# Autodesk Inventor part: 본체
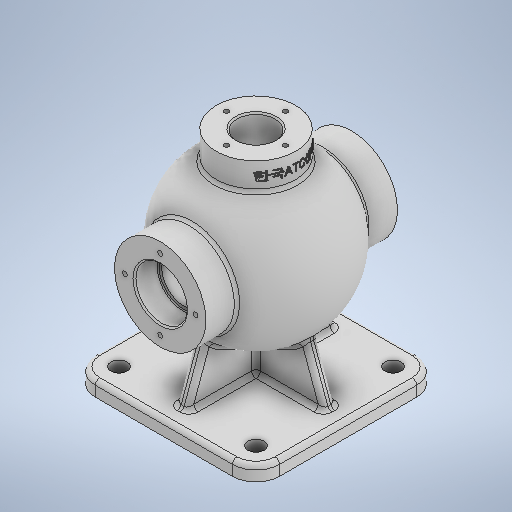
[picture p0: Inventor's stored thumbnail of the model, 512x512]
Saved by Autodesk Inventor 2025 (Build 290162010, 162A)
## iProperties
Created: 2024-07
Part Number: 본체
Material: 일반
Document SubType Name: Modeling
Designer: Admin
Density: 1 g/cm^3
Appearance: 기본값
Author: Admin
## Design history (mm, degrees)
sketch "스케치1"
  geometry: L1 (46.5, 62.5)-(-46.5, 62.5); L2 (-62.5, 46.5)-(-62.5, -46.5); L3 (-46.5, -62.5)-(46.5, -62.5); L4 (62.5, -46.5)-(62.5, 46.5); L5 (62.5, 62.5)-(-62.5, -62.5); L6 (-62.5, 62.5)-(62.5, -62.5); A1 r 16 centre (46.5, -46.5) between (46.5, -62.5) and (62.5, -46.5); A2 r 16 centre (-46.5, -46.5) between (-62.5, -46.5) and (-46.5, -62.5); A3 r 16 centre (-46.5, 46.5) between (-46.5, 62.5) and (-62.5, 46.5); A4 r 16 centre (46.5, 46.5) between (62.5, 46.5) and (46.5, 62.5); 1 further point
  constraints: 12 end point, 8 point on circle, 8 point on line, 8 tangent, 4 centre point, 3 equal radius, 2 midpoint, 2 parallel, 1 horizontal, 1 perpendicular
  dimensions: "d0" = 125 distance of L5.end L6.end; "d1" = 125 distance of L6.end L5.start (= d0); "d2" = 16 radius of A1
extrude "돌출1" new body sketch "스케치1" distance "d3" = 10; taper "d4" = 0 deg
sketch "스케치2"
  geometry: L1 (-50.5, -4)-(50.5, -4); L2 (50.5, -4)-(50.5, 4); L3 (50.5, 4)-(-50.5, 4); L4 (-50.5, 4)-(-50.5, -4); L5 (-50.5, -4)-(50.5, 4); L6 (50.5, -4)-(-50.5, 4); L7 (-4, 50.5)-(4, 50.5); L8 (4, 50.5)-(4, -50.5); L9 (4, -50.5)-(-4, -50.5); L10 (-4, -50.5)-(-4, 50.5); L11 (-4, 50.5)-(4, -50.5); L12 (4, 50.5)-(-4, -50.5); L13 (-62.5, 46.5)-(-62.5, -46.5) reference; L14 (46.5, 62.5)-(-46.5, 62.5) reference; L15 (62.5, -46.5)-(62.5, 46.5) reference; L16 (-46.5, -62.5)-(46.5, -62.5) reference; 5 further points
  constraints: 24 end point, 4 midpoint, 4 parallel, 2 horizontal, 2 perpendicular
  dimensions: "d5" = 8 distance of L3.end L1.start; "d6" = 8 distance of L7.start L7.end; "d7" = 12 distance between parallel lines of L13 L4; "d8" = 12 distance between parallel lines of L14 L7; "d114" = 12 distance between parallel lines of L15 L2 (derived); "d115" = 12 distance between parallel lines of L16 L9 (derived)
extrude "돌출2" join sketch "스케치2" distance "d9" = 85; taper "d10" = 0 deg
sketch "스케치3"
  geometry: L1 (0, 0)-(46.5, 0) reference; L2 (0, 0)-(0, 85) reference; L3 (46.5, 85)-(0, 85) reference; L4 (46.5, 0)-(46.5, 85) reference; L5 (54.5, 0)-(101, 0) reference; L6 (54.5, 0)-(54.5, 85) reference; L7 (101, 85)-(54.5, 85) reference; L8 (101, 0)-(101, 85) reference; L9 (0, 0)-(30.937, 85); L10 (101, 0)-(70.063, 85); L11 (-12, -10)-(-12, 0) reference; L12 (113, -10)-(113, 0) reference; 1 further point
  constraints: 4 end point, 2 point on line
  dimensions: "d11" = 20 deg angle of L11 L9; "d12" = 20 deg angle of L12 L10
extrude "돌출3" cut sketch "스케치3" stored distance "d13" = 85; taper "d14" = 0 deg
sketch "스케치4"
  geometry: L1 (-54.5, 0)-(-8, 0) reference; L2 (-54.5, 0)-(-54.5, 85) reference; L3 (-8, 85)-(-54.5, 85) reference; L4 (-8, 0)-(-8, 85) reference; L5 (0, 0)-(46.5, 0) reference; L6 (0, 0)-(0, 85) reference; L7 (46.5, 85)-(0, 85) reference; L8 (46.5, 0)-(46.5, 85) reference; L9 (-54.5, 0)-(-23.563, 85); L10 (15.563, 85)-(46.5, 0); L11 (-66.5, -10)-(-66.5, 0) reference; L12 (58.5, -10)-(58.5, 0) reference; 1 further point
  constraints: 4 end point, 2 point on line
  dimensions: "d15" = 20 deg angle of L11 L9; "d16" = 20 deg angle of L12 L10
extrude "돌출4" cut sketch "스케치4" distance "d17" = 10; taper "d18" = 0 deg
sketch "스케치5"
  geometry: L1 (-4, 10)-(-4, 95); L2 (4, 10)-(-4, 10); L3 (4, 95)-(4, 10); L4 (-4, 95)-(4, 95); L5 (0, 0)-(0, 85); C1 r 31 at (0, 85)
  constraints: 4 end point, 1 centre point, 1 coincident, 1 parallel
  dimensions: "d23" = 85 distance of L5.start L5.end; "d24" = 62 diameter of C1
extrude "돌출6" join sketch "스케치5" stored distance "d25" = 130; taper "d26" = 0 deg
sketch "스케치7"
  geometry: L1 (0, 0)-(31, 0); L2 (31, 0)-(85, 0); L3 (85, 0)-(127.511, 0); L4 (139, 0)-(31, 0); A1 r 54 centre (85, 0) between (31, 0) and (139, 0); A2 r 54 centre (85, 0) between (139, 0) and (31, 0); 1 further point
  constraints: 8 end point, 4 point on circle, 3 horizontal, 2 centre point, 1 coincident, 1 collinear, 1 point on line
  dimensions: "d27" = 85 distance of L1.start L2.end; "d28" = 108 diameter of A1
revolve "회전1" sketch "스케치7" stored, may be unused: angle "d29" = 90 deg
node "작업 평면1"
sketch "스케치8"
  geometry: C1 r 27 at (0, 0); 1 further point
  constraints: 1 centre point, 1 coincident
  dimensions: "d31" = 54 diameter of C1
extrude "돌출7" join sketch "스케치8" distance "d32" = 65; taper "d33" = 0 deg
fillet "모깎기1" dims "d34" = 3
fillet "모깎기2" dims "d35" = 3
fillet "모깎기3" dims "d36" = 3
sketch "스케치9"
  geometry: C1 r 31 at (0, 0) reference; 2 further points
  constraints: 1 coincident
hole "구멍1" sketch "스케치9" at (0, 0) diameter "d37" = 35; stored, may be unused: countersink angle "d41" = 90 deg, drill point angle "d43" = 0 deg; dims "d38" = 6, "d39" = 4, "d40" = 2, "d42" = 16
sketch "스케치10"
  geometry: C1 r 31 at (0, 0) reference; 2 further points
  constraints: 1 coincident
hole "구멍2" sketch "스케치10" at (0, 0) diameter "d44" = 35; stored, may be unused: countersink angle "d48" = 90 deg, drill point angle "d50" = 0 deg; dims "d45" = 6, "d46" = 4, "d47" = 2, "d49" = 16
sketch "스케치11"
  geometry: C1 r 17.5 at (0, 0) reference; 2 further points
  constraints: 1 coincident
hole "구멍3" sketch "스케치11" at (0, 0) diameter "d51" = 30; stored, may be unused: countersink angle "d55" = 90 deg, drill point angle "d57" = 0 deg; dims "d52" = 6, "d53" = 4, "d54" = 2, "d56" = 16
fillet "모깎기4" dims "d58" = 0.6
sketch "스케치12"
  geometry: C1 r 27 at (0, 0) reference; 2 further points
  constraints: 1 coincident
hole "구멍4" sketch "스케치12" at (0, 0) diameter "d59" = 26; stored, may be unused: countersink angle "d63" = 90 deg, drill point angle "d65" = 0 deg; dims "d60" = 6, "d61" = 4, "d62" = 2, "d64" = 45
chamfer "모따기1" distance "d66" = 1; stored, may be unused: second distance "d67" = 2, angle "d68" = 45 deg
chamfer "모따기2" distance "d69" = 1; stored, may be unused: second distance "d70" = 2, angle "d71" = 45 deg
chamfer "모따기3" distance "d72" = 1; stored, may be unused: second distance "d73" = 2, angle "d74" = 45 deg
sketch "스케치13"
  geometry: L1 (0, 0)-(0, 129); L2 (0, 129)-(0, 41); L3 (0, 129)-(0, 156.877); C1 r 15 at (0, 85) reference; A1 r 44 centre (0, 85) between (0, 129) and (0, 41); A2 r 44 centre (0, 85) between (0, 41) and (0, 129)
  constraints: 6 end point, 4 point on circle, 2 centre point, 2 vertical, 1 coincident, 1 point on line
  dimensions: "d75" = 88 diameter of A1
revolve "회전2" sketch "스케치13" stored, may be unused: angle "d76" = 90 deg
sketch "스케치14" dims "d81" = 48
  geometry: L1 (0, 0)-(0, 24); C1 r 18.5 at (0, 0) reference; 2 further points
  constraints: 2 coincident, 2 end point, 1 vertical, 1 vertical alignment, 2 other
hole "구멍5" sketch "스케치14" at (0, 24) diameter "d82" = 3.242; stored, may be unused: countersink angle "d86" = 90 deg, drill point angle "d88" = 120 deg; dims "d83" = 12, "d84" = 4, "d85" = 2, "d87" = 15
sketch "스케치15" dims "d92" = 40
  geometry: L1 (0, 0)-(0, 20); 2 further points
  constraints: 2 coincident, 2 end point, 1 vertical, 1 vertical alignment, 2 other
hole "구멍6" sketch "스케치15" at (0, 20) diameter "d93" = 3.242; stored, may be unused: countersink angle "d97" = 90 deg, drill point angle "d99" = 120 deg; dims "d94" = 9, "d95" = 4, "d96" = 2, "d98" = 11
node "작업 평면2"
sketch "스케치16"
  geometry: L1 (0, 0)-(199.962, 0); L2 (150, -27)-(150, 27) reference; 1 further point
  constraints: 2 end point, 1 horizontal, 1 point on line, 1 other
  dimensions: "d104" = 9 distance from line of point (141, 0) L2
feature "엠보싱1" sketch "스케치16" dims "d0" = 125, "d1" = 125 (= d0), "d2" = 16, "d5" = 8, "d7" = 12, "d105" = 0.5, "d106" = 0, "d114" = 12 (derived)
sketch "스케치17"
  geometry: A1 r 16 centre (-46.5, 46.5) between (-46.5, 62.5) and (-62.5, 46.5) reference; A2 r 16 centre (-46.5, -46.5) between (-62.5, -46.5) and (-46.5, -62.5) reference; A3 r 16 centre (46.5, -46.5) between (46.5, -62.5) and (62.5, -46.5) reference; A4 r 16 centre (46.5, 46.5) between (62.5, 46.5) and (46.5, 62.5) reference; 5 further points
  constraints: 4 coincident
hole "구멍7" sketch "스케치17" at (-46.5, 46.5), (-46.5, -46.5), (46.5, -46.5), (46.5, 46.5) diameter "d107" = 11; stored, may be unused: countersink angle "d111" = 90 deg, drill point angle "d113" = 0 deg; dims "d108" = 9, "d109" = 4, "d110" = 2, "d112" = 11
node "솔리드1"
pattern_circular "원형 패턴1" dims angle "d90" = 360 deg
mirror "미러1"
pattern_circular "원형 패턴2" dims angle "d101" = 360 deg
node "투영된 루프1"
node "투영된 루프2"
node "투영된 루프3"
node "투영된 루프4"
feature "A9D066F2-1C7D-4E18-AEED-F7BC21143FA4" dims "d37" = 35, "d38" = 6, "d39" = 4, "d40" = 2, "d41" = 90 deg, "d42" = 16, "d43" = 0
other parameters: "d30" = 85, "d77" = 0.5, "d78" = 2, "d79" = 0, "d103" = 327.25
